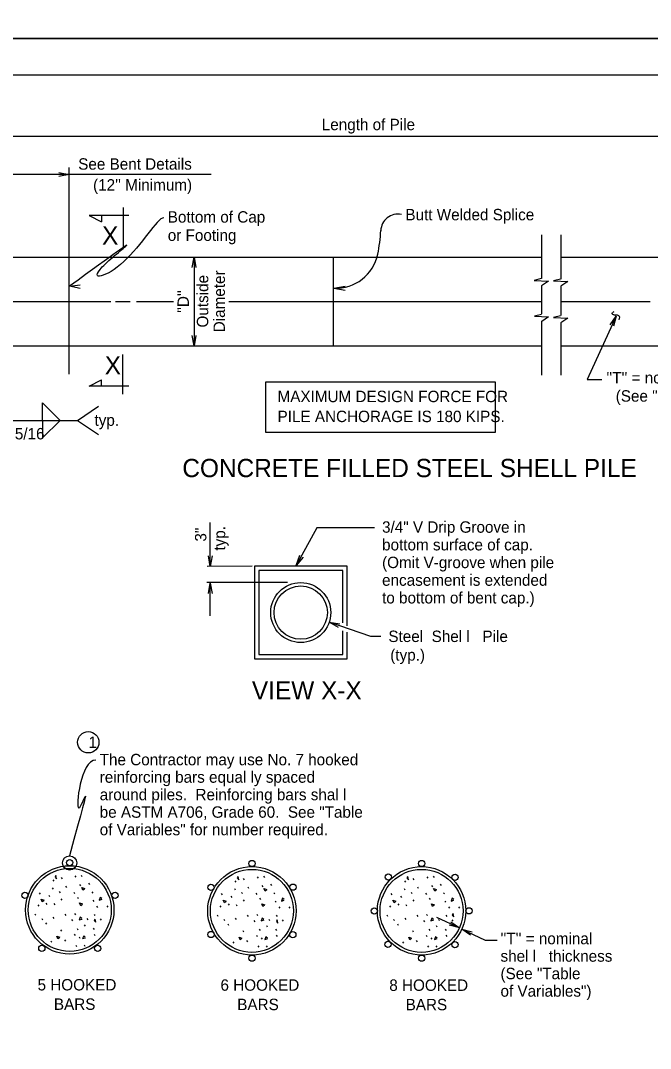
# Model space of a CAD drawing. Extents: x 1053 to 1311, y 5085 to 5337.
# Drawn here: x 1090.2 to 1127, y 5139.9 to 5199.9 of the extents above; entities that cross this region are included whole.
import ezdxf

# ---------------------------------------------------------------- set-up
doc = ezdxf.new("R2010")
doc.units = 0
for name, color, linetype in [('1', 7, 'Continuous'), ('2', 7, 'Continuous'), ('5', 7, 'Continuous'), ('7', 7, 'Continuous'), ('9', 7, 'Continuous'), ('B_Dimension', 7, 'Continuous'), ('B_No_Plot', 7, 'Continuous')]:
    doc.layers.add(name, color=color, linetype=linetype)

msp = doc.modelspace()

# ---------------------------------------------------------------- linework, layer by layer
at = {"layer": '1'}
for p, q in [((1060.921, 5196.747), (1229.529, 5196.747)), ((1087.04, 5193.165), (1136.995, 5193.165)), ((1093.04, 5190.922), (1087.04, 5190.922)), ((1101.34, 5190.922), (1093.04, 5190.922)), ((1096.183, 5188.996), (1096.183, 5186.677)), ((1096.524, 5188.517), (1094.205, 5188.517)), ((1094.923, 5188.517), (1094.923, 5188.146)), ((1120.646, 5187.391), (1120.646, 5184.844)), ((1121.763, 5187.391), (1121.763, 5184.813)), ((1087.04, 5186.086), (1120.646, 5186.086)), ((1100.334, 5186.086), (1100.334, 5180.907)), ((1108.487, 5180.907), (1108.487, 5186.086)), ((1121.763, 5186.086), (1136.995, 5186.086)), ((1108.508, 5184.278), (1109.159, 5184.397)), ((1108.508, 5184.278), (1109.16, 5184.167)), ((1120.646, 5184.42), (1120.646, 5182.776)), ((1121.763, 5184.389), (1121.763, 5182.683)), ((1084.505, 5183.496), (1095.463, 5183.496)), ((1095.738, 5183.496), (1096.595, 5183.496)), ((1096.966, 5183.496), (1099.135, 5183.496)), ((1102.361, 5183.496), (1120.646, 5183.496)), ((1121.763, 5183.496), (1126.993, 5183.496)), ((1120.646, 5182.352), (1120.646, 5179.201)), ((1125.008, 5182.646), (1123.306, 5178.949)), ((1121.763, 5182.249), (1121.763, 5179.201)), ((1087.04, 5180.907), (1120.646, 5180.907)), ((1121.763, 5180.907), (1136.995, 5180.907)), ((1096.174, 5178.077), (1096.174, 5180.396)), ((1094.913, 5178.556), (1094.913, 5178.927)), ((1123.306, 5178.949), (1124.177, 5178.949)), ((1096.514, 5178.556), (1094.195, 5178.556)), ((1091.475, 5177.578), (1092.498, 5176.556)), ((1091.475, 5176.556), (1091.475, 5177.578)), ((1089.179, 5176.556), (1092.498, 5176.556)), ((1091.475, 5176.556), (1091.475, 5175.533)), ((1091.475, 5175.533), (1092.498, 5176.556)), ((1092.498, 5176.556), (1093.526, 5176.556)), ((1101.276, 5168.024), (1101.276, 5170.588)), ((1101.276, 5165.142), (1101.276, 5167.045)), ((1092.56, 5149.838), (1092.614, 5149.763)), ((1093.371, 5149.936), (1093.425, 5149.86)), ((1093.738, 5149.968), (1093.792, 5149.892)), ((1104.019, 5149.883), (1104.073, 5149.808)), ((1104.387, 5149.916), (1104.441, 5149.84)), ((1113.936, 5149.883), (1113.99, 5149.808)), ((1114.304, 5149.916), (1114.358, 5149.84)), ((1092.041, 5149.244), (1092.095, 5149.168)), ((1092.074, 5149.698), (1092.128, 5149.622)), ((1092.82, 5149.341), (1092.874, 5149.266)), ((1093.641, 5149.428), (1093.695, 5149.352)), ((1094.16, 5149.503), (1094.214, 5149.428)), ((1102.722, 5149.646), (1102.776, 5149.57)), ((1103.208, 5149.786), (1103.262, 5149.71)), ((1103.468, 5149.289), (1103.522, 5149.213)), ((1104.289, 5149.375), (1104.343, 5149.3)), ((1104.808, 5149.451), (1104.862, 5149.375)), ((1112.639, 5149.646), (1112.693, 5149.57)), ((1113.126, 5149.786), (1113.18, 5149.71)), ((1113.385, 5149.289), (1113.439, 5149.213)), ((1114.207, 5149.375), (1114.261, 5149.3)), ((1114.725, 5149.451), (1114.779, 5149.375)), ((1091.274, 5148.952), (1091.328, 5148.876)), ((1091.836, 5148.801), (1091.89, 5148.725)), ((1092.452, 5149.028), (1092.506, 5148.952)), ((1093.295, 5148.985), (1093.349, 5148.909)), ((1093.511, 5148.693), (1093.565, 5148.617)), ((1094.354, 5149.006), (1094.409, 5148.93)), ((1101.922, 5148.9), (1101.976, 5148.824)), ((1102.484, 5148.748), (1102.538, 5148.673)), ((1102.69, 5149.192), (1102.744, 5149.116)), ((1103.1, 5148.975), (1103.154, 5148.9)), ((1103.943, 5148.932), (1103.997, 5148.856)), ((1104.16, 5148.64), (1104.214, 5148.565)), ((1105.003, 5148.954), (1105.057, 5148.878)), ((1111.839, 5148.9), (1111.893, 5148.824)), ((1112.401, 5148.748), (1112.455, 5148.673)), ((1112.607, 5149.192), (1112.661, 5149.116)), ((1113.018, 5148.975), (1113.072, 5148.9)), ((1113.861, 5148.932), (1113.915, 5148.856)), ((1114.077, 5148.64), (1114.131, 5148.565)), ((1114.92, 5148.954), (1114.974, 5148.878)), ((1091.198, 5148.239), (1091.252, 5148.163)), ((1091.674, 5148.347), (1091.728, 5148.271)), ((1092.139, 5148.314), (1092.193, 5148.239)), ((1092.549, 5148.595), (1092.603, 5148.52)), ((1094.419, 5148.52), (1094.473, 5148.444)), ((1094.636, 5148.174), (1094.69, 5148.098)), ((1095.23, 5148.185), (1095.284, 5148.109)), ((1101.847, 5148.186), (1101.901, 5148.111)), ((1102.322, 5148.294), (1102.376, 5148.219)), ((1102.787, 5148.262), (1102.841, 5148.186)), ((1103.198, 5148.543), (1103.252, 5148.467)), ((1105.068, 5148.467), (1105.122, 5148.392)), ((1105.284, 5148.121), (1105.338, 5148.046)), ((1105.878, 5148.132), (1105.932, 5148.057)), ((1111.764, 5148.186), (1111.818, 5148.111)), ((1112.239, 5148.294), (1112.293, 5148.219)), ((1112.704, 5148.262), (1112.758, 5148.186)), ((1113.115, 5148.543), (1113.169, 5148.467)), ((1114.985, 5148.467), (1115.039, 5148.392)), ((1115.201, 5148.121), (1115.255, 5148.046)), ((1115.795, 5148.132), (1115.849, 5148.057)), ((1091.025, 5147.709), (1091.079, 5147.633)), ((1091.425, 5147.45), (1091.479, 5147.374)), ((1092.085, 5147.525), (1092.139, 5147.45)), ((1092.787, 5147.698), (1092.841, 5147.623)), ((1093.349, 5147.741), (1093.403, 5147.666)), ((1094.063, 5147.45), (1094.117, 5147.374)), ((1094.484, 5147.687), (1094.538, 5147.612)), ((1094.841, 5147.428), (1094.895, 5147.352)), ((1101.674, 5147.657), (1101.728, 5147.581)), ((1102.733, 5147.473), (1102.787, 5147.397)), ((1103.435, 5147.646), (1103.489, 5147.57)), ((1103.997, 5147.689), (1104.052, 5147.613)), ((1105.132, 5147.635), (1105.187, 5147.559)), ((1111.591, 5147.657), (1111.645, 5147.581)), ((1112.65, 5147.473), (1112.704, 5147.397)), ((1113.353, 5147.646), (1113.407, 5147.57)), ((1113.915, 5147.689), (1113.969, 5147.613)), ((1115.05, 5147.635), (1115.104, 5147.559)), ((1091.652, 5147.19), (1091.706, 5147.114)), ((1093.176, 5147.385), (1093.23, 5147.309)), ((1093.49, 5146.866), (1093.544, 5146.79)), ((1093.911, 5147.082), (1093.965, 5147.006)), ((1094.441, 5146.877), (1094.495, 5146.801)), ((1102.073, 5147.397), (1102.128, 5147.321)), ((1102.3, 5147.138), (1102.354, 5147.062)), ((1103.825, 5147.332), (1103.879, 5147.257)), ((1104.56, 5147.03), (1104.614, 5146.954)), ((1104.711, 5147.397), (1104.765, 5147.321)), ((1105.489, 5147.376), (1105.543, 5147.3)), ((1111.991, 5147.397), (1112.045, 5147.321)), ((1112.218, 5147.138), (1112.272, 5147.062)), ((1113.742, 5147.332), (1113.796, 5147.257)), ((1114.477, 5147.03), (1114.531, 5146.954)), ((1114.628, 5147.397), (1114.682, 5147.321)), ((1115.406, 5147.376), (1115.46, 5147.3)), ((1092.528, 5146.79), (1092.582, 5146.715)), ((1093.328, 5146.531), (1093.382, 5146.455)), ((1093.609, 5146.369), (1093.663, 5146.293)), ((1094.484, 5146.531), (1094.538, 5146.455)), ((1103.176, 5146.738), (1103.23, 5146.662)), ((1103.976, 5146.478), (1104.03, 5146.403)), ((1104.138, 5146.814), (1104.192, 5146.738)), ((1104.257, 5146.316), (1104.311, 5146.241)), ((1105.089, 5146.824), (1105.143, 5146.749)), ((1105.132, 5146.478), (1105.187, 5146.403)), ((1113.093, 5146.738), (1113.147, 5146.662)), ((1113.893, 5146.478), (1113.947, 5146.403)), ((1114.055, 5146.814), (1114.109, 5146.738)), ((1114.174, 5146.316), (1114.228, 5146.241)), ((1115.006, 5146.824), (1115.06, 5146.749)), ((1115.05, 5146.478), (1115.104, 5146.403)), ((1091.955, 5146.131), (1092.009, 5146.055)), ((1092.755, 5146.207), (1092.809, 5146.131)), ((1093.414, 5145.893), (1093.468, 5145.817)), ((1093.901, 5145.904), (1093.955, 5145.828)), ((1102.603, 5146.079), (1102.657, 5146.003)), ((1103.403, 5146.154), (1103.457, 5146.079)), ((1104.062, 5145.841), (1104.116, 5145.765)), ((1104.549, 5145.852), (1104.603, 5145.776)), ((1112.52, 5146.079), (1112.574, 5146.003)), ((1113.32, 5146.154), (1113.374, 5146.079)), ((1113.98, 5145.841), (1114.034, 5145.765)), ((1114.466, 5145.852), (1114.52, 5145.776)), ((1117.35, 5146.184), (1118.057, 5146.184))]:
    msp.add_line(p, q, dxfattribs=at)
for points in [[(1100.228, 5185.484), (1100.334, 5186.086), (1100.44, 5185.484)], [(1120.628, 5184.837), (1120.214, 5184.733), (1121.041, 5184.692), (1120.649, 5184.423)], [(1121.76, 5184.811), (1121.347, 5184.707), (1122.174, 5184.666), (1121.781, 5184.397)], [(1120.643, 5182.742), (1120.23, 5182.639), (1121.057, 5182.598), (1120.664, 5182.329)], [(1121.76, 5182.665), (1121.347, 5182.562), (1122.174, 5182.52), (1121.781, 5182.251)], [(1124.66, 5182.144), (1125.008, 5182.646), (1124.853, 5182.055)], [(1100.44, 5181.509), (1100.334, 5180.907), (1100.228, 5181.509)], [(1101.385, 5168.64), (1101.276, 5168.024), (1101.168, 5168.64)], [(1106.7, 5168.567), (1106.309, 5168.079), (1106.509, 5168.671)], [(1101.168, 5166.43), (1101.276, 5167.046), (1101.385, 5166.43)], [(1108.774, 5164.459), (1108.227, 5164.761), (1108.845, 5164.665)], [(1092.249, 5149.962), (1092.206, 5149.865), (1092.292, 5149.768), (1092.26, 5149.962)], [(1102.898, 5149.91), (1102.854, 5149.813), (1102.941, 5149.715), (1102.908, 5149.91)], [(1112.815, 5149.91), (1112.771, 5149.813), (1112.858, 5149.715), (1112.826, 5149.91)], [(1093.933, 5149.168), (1093.836, 5149.093), (1093.771, 5149.255), (1093.944, 5149.201)], [(1094.949, 5148.606), (1094.852, 5148.682), (1094.787, 5148.52), (1094.96, 5148.574)], [(1104.581, 5149.116), (1104.484, 5149.04), (1104.419, 5149.202), (1104.592, 5149.148)], [(1105.597, 5148.554), (1105.5, 5148.63), (1105.435, 5148.467), (1105.608, 5148.521)], [(1114.498, 5149.116), (1114.401, 5149.04), (1114.336, 5149.202), (1114.509, 5149.148)], [(1115.514, 5148.554), (1115.417, 5148.63), (1115.352, 5148.467), (1115.525, 5148.521)], [(1091.555, 5148.487), (1091.458, 5148.412), (1091.393, 5148.574), (1091.566, 5148.52)], [(1093.803, 5148.271), (1093.706, 5148.195), (1093.641, 5148.358), (1093.814, 5148.303)], [(1102.203, 5148.435), (1102.106, 5148.359), (1102.041, 5148.521), (1102.214, 5148.467)], [(1104.451, 5148.219), (1104.354, 5148.143), (1104.289, 5148.305), (1104.462, 5148.251)], [(1112.12, 5148.435), (1112.023, 5148.359), (1111.958, 5148.521), (1112.131, 5148.467)], [(1114.369, 5148.219), (1114.271, 5148.143), (1114.207, 5148.305), (1114.379, 5148.251)], [(1093.771, 5147.45), (1093.674, 5147.525), (1093.609, 5147.363), (1093.782, 5147.417)], [(1104.419, 5147.397), (1104.322, 5147.473), (1104.257, 5147.311), (1104.43, 5147.365)], [(1114.336, 5147.397), (1114.239, 5147.473), (1114.174, 5147.311), (1114.347, 5147.365)], [(1115.469, 5147.747), (1115.426, 5147.649), (1115.512, 5147.552), (1115.48, 5147.747)], [(1094.538, 5147.417), (1094.495, 5147.32), (1094.581, 5147.223), (1094.549, 5147.417)], [(1105.187, 5147.365), (1105.143, 5147.268), (1105.23, 5147.17), (1105.197, 5147.365)], [(1092.474, 5146.326), (1092.376, 5146.25), (1092.312, 5146.412), (1092.485, 5146.358)], [(1093.976, 5146.358), (1093.879, 5146.434), (1093.814, 5146.272), (1093.987, 5146.326)], [(1103.122, 5146.273), (1103.025, 5146.197), (1102.96, 5146.36), (1103.133, 5146.305)], [(1104.625, 5146.306), (1104.527, 5146.381), (1104.462, 5146.219), (1104.635, 5146.273)], [(1113.039, 5146.273), (1112.942, 5146.197), (1112.877, 5146.36), (1113.05, 5146.305)], [(1114.542, 5146.306), (1114.444, 5146.381), (1114.38, 5146.219), (1114.552, 5146.273)]]:
    msp.add_lwpolyline(points, dxfattribs=at)
for centre, radius in [((1093.058, 5150.691), 0.415), ((1093.066, 5147.946), 2.583), ((1093.066, 5150.712), 0.183), ((1103.714, 5147.894), 2.583), ((1103.714, 5150.66), 0.183), ((1113.631, 5147.894), 2.583), ((1113.631, 5150.66), 0.183), ((1093.066, 5147.946), 2.425), ((1103.714, 5147.894), 2.425), ((1113.631, 5147.894), 2.425), ((1111.684, 5149.865), 0.183), ((1115.587, 5149.85), 0.183), ((1101.317, 5149.273), 0.183), ((1106.109, 5149.277), 0.183), ((1090.447, 5148.805), 0.183), ((1095.714, 5148.8), 0.183), ((1110.865, 5147.889), 0.183), ((1116.397, 5147.894), 0.183), ((1101.319, 5146.511), 0.183), ((1106.107, 5146.507), 0.183), ((1091.434, 5145.709), 0.183), ((1094.7, 5145.703), 0.183), ((1111.665, 5145.941), 0.183), ((1115.582, 5145.921), 0.183), ((1103.714, 5145.128), 0.183), ((1113.631, 5145.128), 0.183)]:
    msp.add_circle(centre, radius, dxfattribs=at)
for centre, radius, start, end in [((1112.25, 5187.608), 1.002, 78.58964, 178.24888), ((1101.148, 5188.231), 10.117, 348.78966, 356.64738), ((1108.625, 5186.776), 2.501, 267.31611, 348.17849)]:
    msp.add_arc(centre, radius, start, end, dxfattribs=at)
msp.add_spline([(1125.172, 5182.432), (1125.213, 5182.577), (1125.192, 5182.618), (1125.13, 5182.68), (1125.047, 5182.701), (1124.965, 5182.701), (1124.861, 5182.721), (1124.82, 5182.742), (1124.779, 5182.784), (1124.779, 5182.825), (1124.82, 5182.866), (1124.882, 5182.908)], degree=3, dxfattribs=at)
at = {"layer": '2'}
for p, q in [((1094.205, 5188.517), (1094.923, 5188.146)), ((1094.195, 5178.556), (1094.913, 5178.927))]:
    msp.add_line(p, q, dxfattribs=at)
at = {"layer": '5'}
for p, q in [((1107.508, 5170.27), (1106.309, 5168.079)), ((1110.878, 5170.27), (1107.508, 5170.27)), ((1103.733, 5168.029), (1101.091, 5168.024)), ((1105.792, 5167.075), (1101.08, 5167.075)), ((1110.66, 5163.93), (1108.227, 5164.761)), ((1111.258, 5163.93), (1110.66, 5163.93))]:
    msp.add_line(p, q, dxfattribs=at)
at = {"layer": '7'}
for p, q in [((1093.04, 5179.255), (1093.04, 5191.324)), ((1093.526, 5176.556), (1094.739, 5177.384)), ((1093.526, 5176.556), (1094.739, 5175.727)), ((1114.498, 5147.532), (1115.842, 5146.896)), ((1115.984, 5146.829), (1117.35, 5146.184))]:
    msp.add_line(p, q, dxfattribs=at)
msp.add_lwpolyline([(1104.526, 5178.814), (1117.935, 5178.814), (1117.935, 5175.848), (1104.526, 5175.848)], close=True, dxfattribs=at)
for centre, radius in [((1106.566, 5165.322), 1.753), ((1106.566, 5165.322), 1.557), ((1094.147, 5157.745), 0.625)]:
    msp.add_circle(centre, radius, dxfattribs=at)
for points in [[(1098.564, 5188.394), (1098.193, 5188.394), (1096.28, 5185.138), (1093.055, 5184.396), (1098.564, 5188.394), (1093.055, 5184.396)], [(1094.583, 5156.701), (1093.712, 5156.701), (1093.051, 5151.11), (1094.583, 5156.701), (1093.051, 5151.11)]]:
    msp.add_open_spline(points, degree=3, dxfattribs=at)
at = {"layer": '9'}
for p, q in [((1109.273, 5168.029), (1103.859, 5168.029)), ((1103.859, 5168.029), (1103.859, 5162.615)), ((1109.273, 5164.542), (1109.273, 5168.029)), ((1104.109, 5167.779), (1104.109, 5162.865)), ((1109.023, 5167.779), (1104.109, 5167.779)), ((1109.023, 5164.732), (1109.023, 5167.779)), ((1109.023, 5162.865), (1109.023, 5164.256)), ((1109.273, 5162.615), (1109.273, 5164.175)), ((1103.859, 5162.615), (1109.273, 5162.615)), ((1104.109, 5162.865), (1109.023, 5162.865))]:
    msp.add_line(p, q, dxfattribs=at)
at = {"layer": 'B_Dimension'}
for points in [[(1092.424, 5191.03), (1093.04, 5190.922), (1092.424, 5190.813)], [(1093.665, 5184.261), (1093.055, 5184.396), (1093.674, 5184.478)], [(1115.332, 5147.257), (1115.842, 5146.896), (1115.239, 5147.061)], [(1116.495, 5146.468), (1115.984, 5146.829), (1116.587, 5146.664)]]:
    msp.add_lwpolyline(points, dxfattribs=at)
at = {"layer": 'B_No_Plot'}
for points in [[(1053.308, 5312.654), (1231.974, 5312.654), (1231.974, 5198.862), (1053.308, 5198.862)], [(1053.308, 5198.862), (1231.974, 5198.862), (1231.974, 5085.07), (1053.308, 5085.07)]]:
    msp.add_lwpolyline(points, close=True, dxfattribs=at)

# ---------------------------------------------------------------- texts
at = {"layer": '1'}
for s, height, p in [('Length of Pile', 0.66667, (1107.797, 5193.511)), ("(12'' Minimum)", 0.66667, (1094.429, 5189.982)), ('Butt Welded Splice', 0.66667, (1112.686, 5188.244)), ('Bottom of Cap ', 0.66667, (1098.795, 5188.109)), ('or Footing', 0.6667, (1098.795, 5187.042)), ("''T'' = nominal  shel l  thickness", 0.66667, (1124.434, 5178.715)), ('MAXIMUM DESIGN FORCE FOR', 0.66667, (1105.213, 5177.619)), ('(See "Table of Variables")', 0.66667, (1124.98, 5177.648)), ('typ.', 0.6667, (1094.512, 5176.233)), ('PILE ANCHORAGE IS 180 KIPS.', 0.66667, (1105.213, 5176.452)), ('5/16', 0.6667, (1089.857, 5175.443)), ('1', 0.665, (1094.162, 5157.414)), ('The Contractor may use No. 7 hooked', 0.66658, (1094.816, 5156.4)), ('reinforcing bars equal ly spaced ', 0.66658, (1094.816, 5155.378)), ('around piles.  Reinforcing bars shal l   ', 0.66658, (1094.816, 5154.356)), ('be ASTM A706, Grade 60.  See "Table', 0.66658, (1094.816, 5153.334)), ('of Variables" for number required.', 0.66658, (1094.816, 5152.311)), ("''T'' = nominal   ", 0.66658, (1118.244, 5145.943)), ('shel l   thickness ', 0.66658, (1118.244, 5144.921)), ('(See "Table', 0.66658, (1118.244, 5143.899)), ('5 HOOKED', 0.6666, (1091.184, 5143.242)), ('6 HOOKED', 0.6666, (1101.876, 5143.225)), ('8 HOOKED', 0.6666, (1111.744, 5143.217)), ('of Variables")', 0.66658, (1118.244, 5142.877)), ('BARS', 0.6666, (1092.139, 5142.109)), ('BARS', 0.6666, (1102.856, 5142.091)), ('BARS', 0.6666, (1112.699, 5142.084))]:
    msp.add_text(s, height=height, dxfattribs=at).set_placement(p)
for s, p in [('Diameter', (1102.135, 5181.701)), ('Outside', (1101.162, 5181.979)), ("''D''", (1100.03, 5182.833))]:
    msp.add_text(s, height=0.6667, rotation=90, dxfattribs=at).set_placement(p)
at = {"layer": '7'}
for s, height, p in [('See Bent Details', 0.66667, (1093.56, 5191.203)), ('CONCRETE FILLED STEEL SHELL PILE', 1.067, (1099.646, 5173.236)), ('3/4" V Drip Groove in ', 0.66667, (1111.322, 5169.988)), ('bottom surface of cap.', 0.66667, (1111.322, 5168.955)), ('(Omit V-groove when pile', 0.66667, (1111.322, 5167.921)), ('encasement is extended', 0.66667, (1111.322, 5166.888)), ('to bottom of bent cap.)', 0.66667, (1111.322, 5165.855)), ('Steel  Shel l   Pile', 0.66667, (1111.691, 5163.602)), ('(typ.)', 0.6667, (1111.8, 5162.515))]:
    msp.add_text(s, height=height, dxfattribs=at).set_placement(p)
for s, height, rotation, p in [('X', 1.067, 360, (1094.953, 5186.824)), ('X', 1.067, 360, (1095.11, 5179.237)), ('typ.', 0.6667, 90, (1102.154, 5168.941)), ('3"', 0.6667, 90, (1101.053, 5169.47))]:
    msp.add_text(s, height=height, rotation=rotation, dxfattribs=at).set_placement(p)
at = {"layer": '9'}
msp.add_text('VIEW X-X', height=1.067, dxfattribs=at).set_placement((1103.713, 5160.244))

doc.saveas('drawing.dxf')
